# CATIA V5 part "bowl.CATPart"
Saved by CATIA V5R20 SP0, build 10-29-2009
Part number: bowl
Material "Grey Blue": density 7860 kg/m3, Young's modulus 2e+11 Pa, Poisson ratio 0.266
Bounding box of the stored display mesh (mm): x -60 to 60, y -60 to 59.999, z 0 to 40
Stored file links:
  E:\设计\180212313林恺昇\bowl.CATPart
  E:\设计\180212313林恺昇\Product1.CATProduct
  E:\设计\180212313林恺昇\cart3.CATPart
  C:\Program Files\Dassault Systemes\B20\intel_a\startup\materials\Catalog.CATMaterial
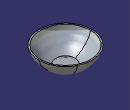
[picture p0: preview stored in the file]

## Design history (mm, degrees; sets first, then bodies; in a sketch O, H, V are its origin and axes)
Body1 (main body)
  Sketch1 on xy-plane, origin (0, 0, 0), H (1, 0, 0), V (0, 1, 0)
    circle A1 centre (0, 0) radius 22.5
    radius A1 = 22.5
  Plane1: type Offset, RefPlane xy-plane, Offset 10
  Plane2: type Offset, RefPlane Plane1, Offset 10
  Plane3: type Offset, RefPlane Plane2, Offset 10
  Plane4: type Offset, RefPlane Plane3, Offset 10
  Sketch2 on Plane4, origin (0, 0, 40), H (1, 0, 0), V (0, 1, 0)
    circle A1 centre (0, 0) radius 60
    radius A1 = 60
  Sketch3 on Plane3, origin (0, 0, 30), H (1, 0, 0), V (0, 1, 0)
    circle A1 centre (0, 0) radius 56.5
    radius A1 = 56.5
  Sketch4 on Plane2, origin (0, 0, 20), H (1, 0, 0), V (0, 1, 0)
    circle A1 centre (0, 0) radius 49
    radius A1 = 49
  Sketch5 on Plane1, origin (0, 0, 10), H (1, 0, 0), V (0, 1, 0)
    circle A1 centre (0, 0) radius 40
    radius A1 = 40
  Loft1: solid, Sections (Sketch2; Sketch3; Sketch4; Sketch5; Sketch1)
  Shell1: ExtOffset 0, Face face of Loft1, IntOffset 3
  Sketch6 on face of Loft1, origin (0, 0, 0), H (1, 0, 0), V (0, -1, 0)
    circle A1 centre (0, 0) radius 20
    radius A1 = 20
  Pocket1: profile Sketch6, direction (0, 0, 1), length 2
  Fillet1: radius 1, on edge [face of Pocket1 from Sketch6.A1 | end face of Pocket1]
  Fillet2: radius 1, on edge [face of Loft1 | face of Pocket1 from Sketch6.A1]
